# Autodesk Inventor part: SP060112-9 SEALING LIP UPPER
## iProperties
Created: 2011-07
Part Number: SP060112-9 SEALING LIP UPPER
Material: Rubber
Document SubType Name: Modeling
Designer: Administrator
Density: 0.93 g/cm^3
Mass: 12.518 g
Surface Area: 111.022 cm^2
Volume: 13.4602 cm^3
Author: Administrator
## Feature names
1. Extrusion1
2. Extrusion4
